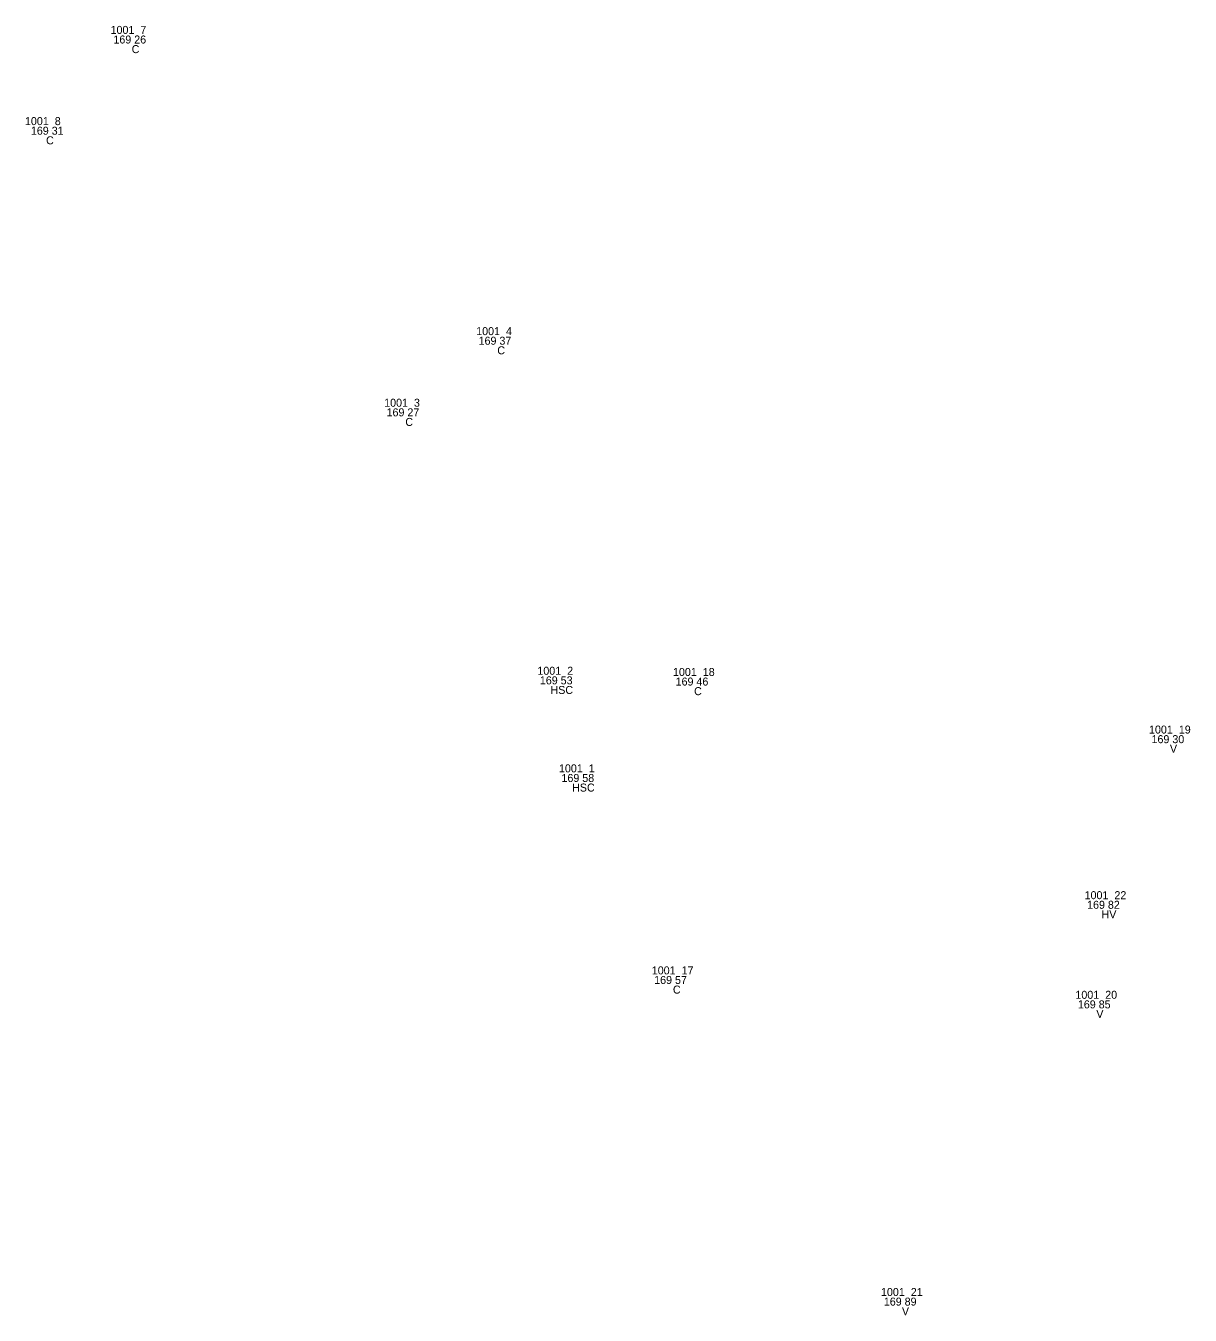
# Model space of a CAD drawing. Extents: x -607541 to -607268, y -1195145 to -1195000.
# Drawn here: x -607511.44 to -607482.33, y -1195047.24 to -1195015.01 of the extents above; entities that cross this region are included whole.
import ezdxf

# ---------------------------------------------------------------- set-up
doc = ezdxf.new("R2010")
doc.units = 0
for name, color, linetype in [('Vrstva 20', 7, 'Continuous'), ('Vrstva 21', 7, 'Continuous'), ('Vrstva 22', 7, 'Continuous'), ('Vrstva 23', 7, 'Continuous'), ('Vrstva 24', 7, 'Continuous')]:
    doc.layers.add(name, color=color, linetype=linetype)

msp = doc.modelspace()

# ---------------------------------------------------------------- linework, layer by layer
at = {"layer": 'Vrstva 20'}
for p, q in [((-607508.65, -1195015.35), (-607508.65, -1195015.35)), ((-607510.79, -1195017.63), (-607510.79, -1195017.63)), ((-607499.51, -1195022.88), (-607499.51, -1195022.88)), ((-607501.81, -1195024.67), (-607501.81, -1195024.67)), ((-607497.98, -1195031.37), (-607497.98, -1195031.37)), ((-607494.59, -1195031.4), (-607494.59, -1195031.4)), ((-607482.69, -1195032.84), (-607482.69, -1195032.84)), ((-607497.44, -1195033.81), (-607497.44, -1195033.81)), ((-607484.3, -1195036.98), (-607484.3, -1195036.98)), ((-607495.12, -1195038.86), (-607495.12, -1195038.86)), ((-607484.53, -1195039.47), (-607484.53, -1195039.47)), ((-607489.39, -1195046.9), (-607489.39, -1195046.9))]:
    msp.add_line(p, q, dxfattribs=at)

# ---------------------------------------------------------------- texts
at = {"layer": 'Vrstva 21'}
for p in [(-607509.321, -1195015.21), (-607511.461, -1195017.49), (-607500.181, -1195022.74), (-607502.481, -1195024.53), (-607498.651, -1195031.23), (-607495.261, -1195031.26), (-607483.361, -1195032.7), (-607498.111, -1195033.67), (-607484.971, -1195036.84), (-607495.791, -1195038.72), (-607485.201, -1195039.33), (-607490.061, -1195046.76)]:
    msp.add_text('1001 ', height=0.2, dxfattribs=at).set_placement(p)
at = {"layer": 'Vrstva 22'}
for s, p in [(' 7', (-607508.65, -1195015.21)), (' 8', (-607510.79, -1195017.49)), (' 4', (-607499.51, -1195022.74)), (' 3', (-607501.81, -1195024.53)), (' 2', (-607497.98, -1195031.23)), (' 18', (-607494.59, -1195031.26)), (' 19', (-607482.69, -1195032.7)), (' 1', (-607497.44, -1195033.67)), (' 22', (-607484.3, -1195036.84)), (' 17', (-607495.12, -1195038.72)), (' 20', (-607484.53, -1195039.33)), (' 21', (-607489.39, -1195046.76))]:
    msp.add_text(s, height=0.2, dxfattribs=at).set_placement(p)
at = {"layer": 'Vrstva 23'}
for s, p in [('169 26 ', (-607509.25, -1195015.45)), ('169 31 ', (-607511.313, -1195017.73)), ('169 37 ', (-607500.121, -1195022.98)), ('169 27 ', (-607502.421, -1195024.77)), ('169 53 ', (-607498.589, -1195031.47)), ('169 46 ', (-607495.195, -1195031.5)), ('169 30 ', (-607483.298, -1195032.94)), ('169 58 ', (-607498.049, -1195033.91)), ('169 82 ', (-607484.909, -1195037.08)), ('169 57 ', (-607495.731, -1195038.96)), ('169 85 ', (-607485.139, -1195039.57)), ('169 89 ', (-607489.99, -1195047))]:
    msp.add_text(s, height=0.2, dxfattribs=at).set_placement(p)
at = {"layer": 'Vrstva 24'}
for s, p in [('C ', (-607508.793, -1195015.69)), ('C ', (-607510.933, -1195017.97)), ('C ', (-607499.653, -1195023.22)), ('C ', (-607501.953, -1195025.01)), ('HSC ', (-607498.323, -1195031.71)), ('C ', (-607494.733, -1195031.74)), ('V ', (-607482.838, -1195033.18)), ('HSC ', (-607497.783, -1195034.15)), ('HV ', (-607484.548, -1195037.32)), ('C ', (-607495.263, -1195039.2)), ('V ', (-607484.678, -1195039.81)), ('V ', (-607489.538, -1195047.24))]:
    msp.add_text(s, height=0.2, dxfattribs=at).set_placement(p)

doc.saveas('drawing.dxf')
